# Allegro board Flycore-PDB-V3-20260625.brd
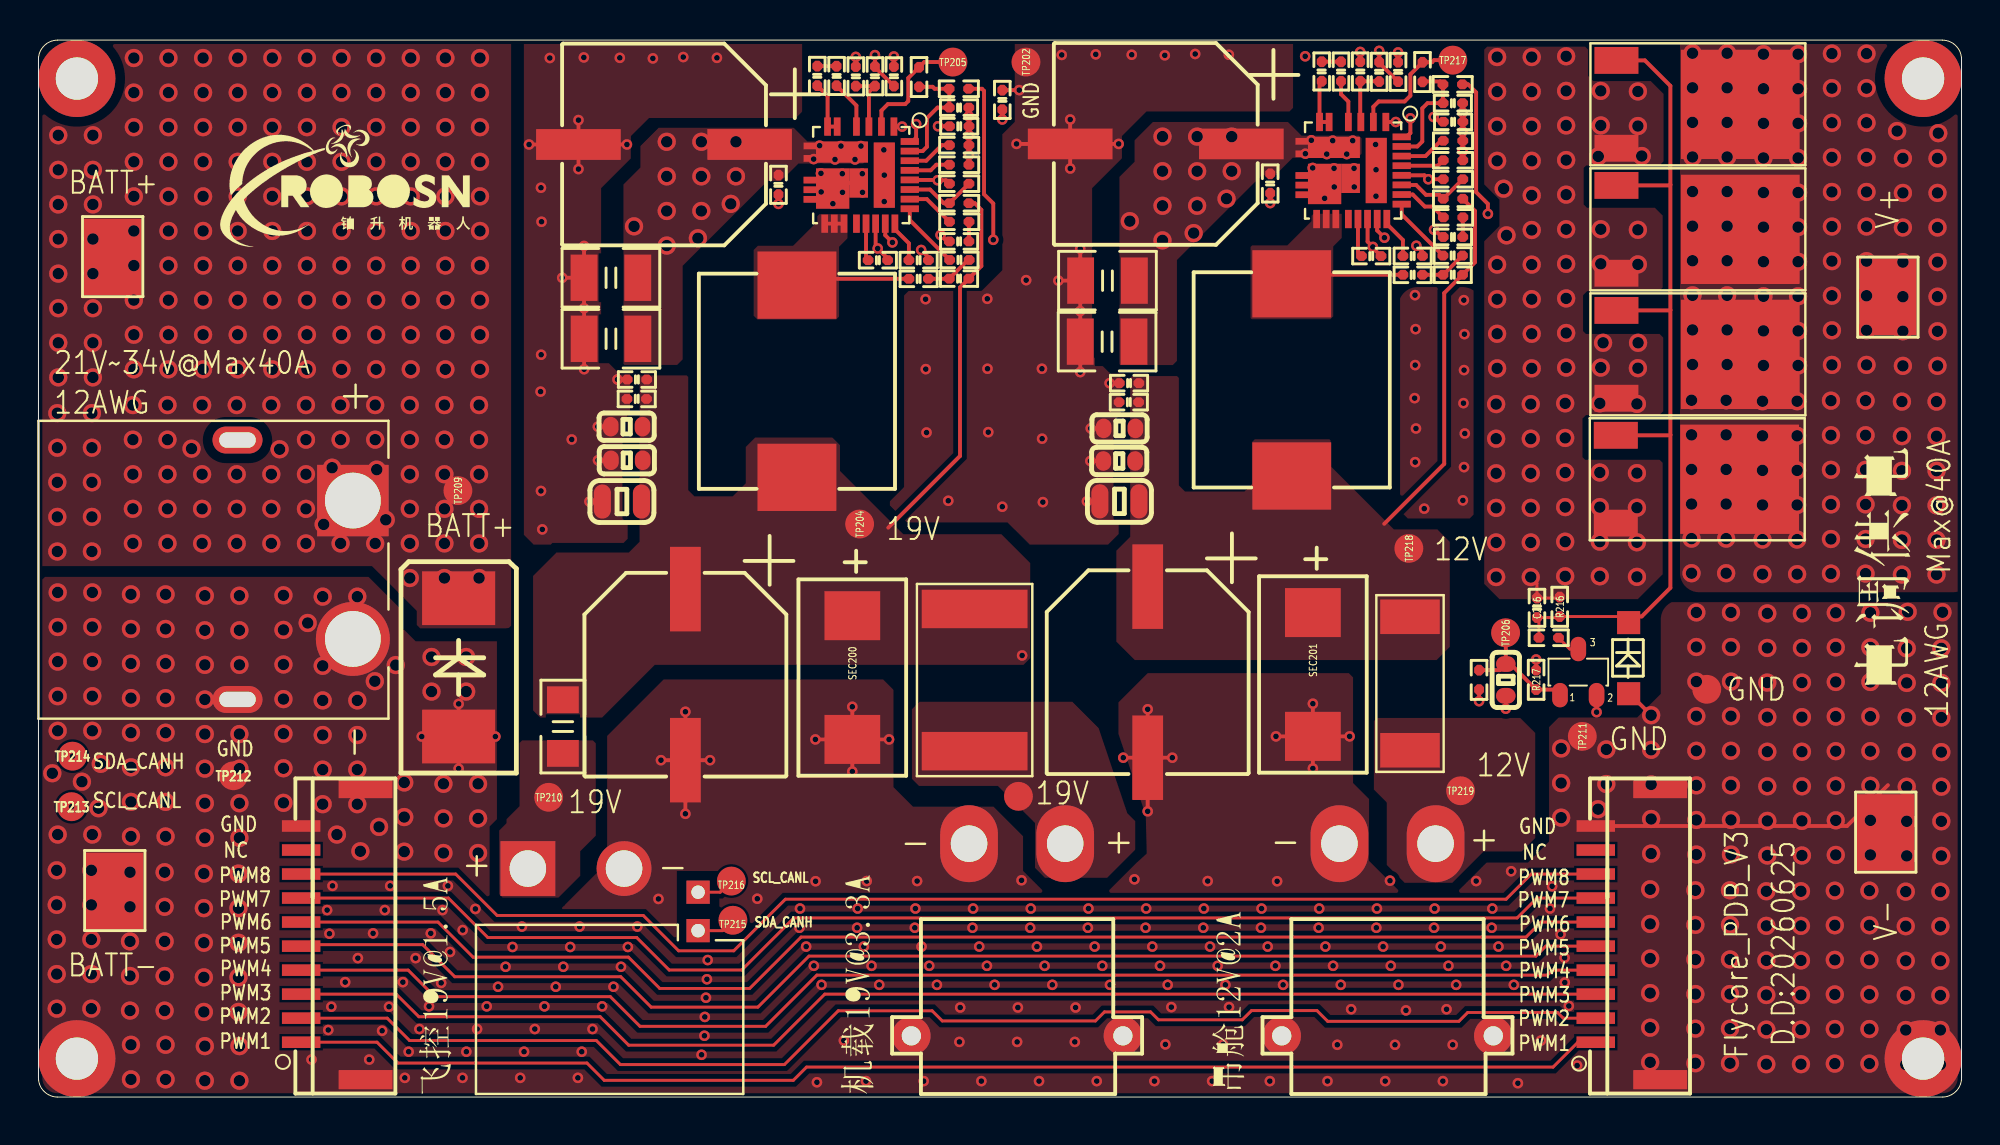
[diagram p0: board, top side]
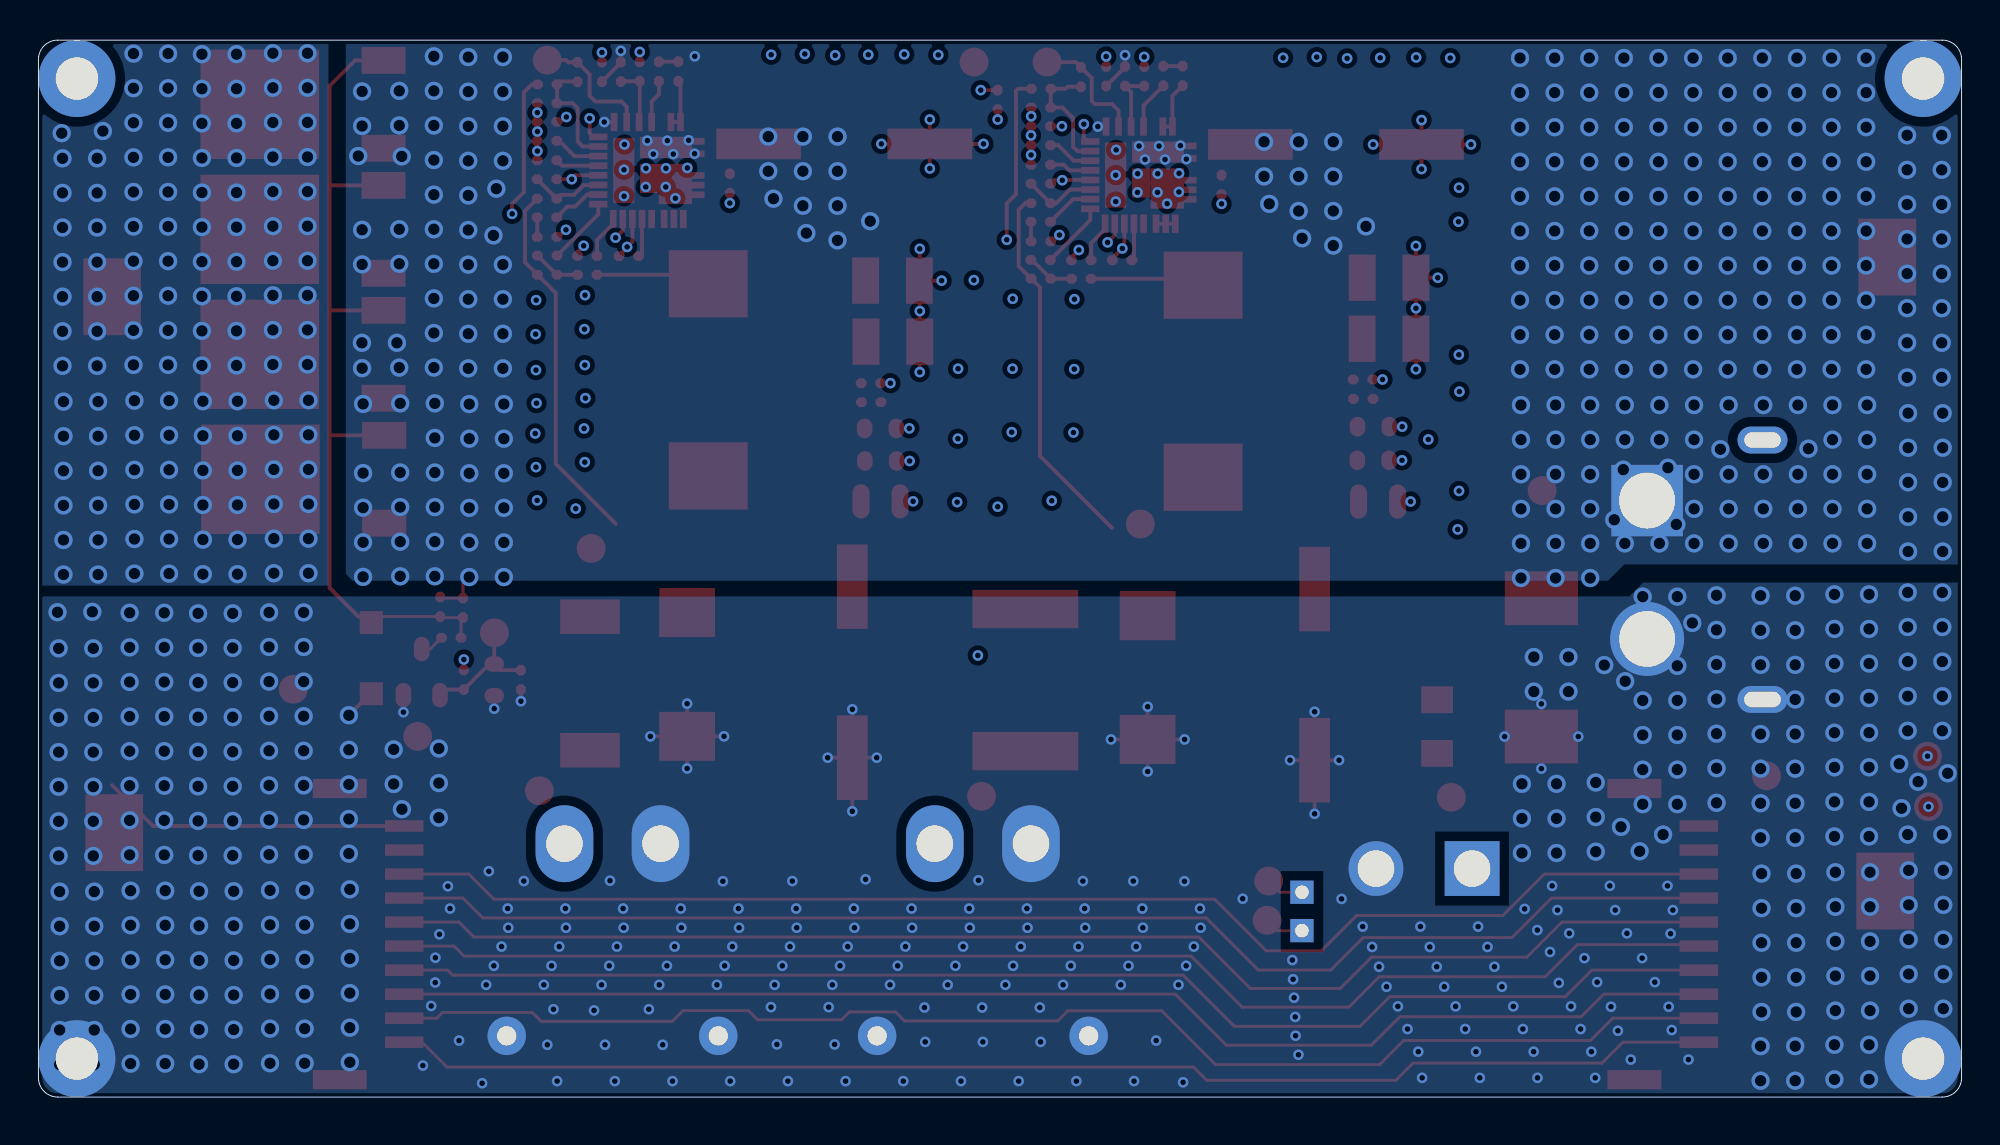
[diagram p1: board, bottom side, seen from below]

Outline 100 x 55 mm; copper layers: TOP, PWR02, PWR03, PWR04, PWR05, BOTTOM. Coordinates in mm from the lower left corner of the outline.
Outline path: 0,54 0,1 arc(0.29,0.29) 1,0 99,0 arc(99.71,0.29) 100,1 100,54 arc(99.71,54.71) 99,55 1,55 arc(0.29,54.71) 0,54

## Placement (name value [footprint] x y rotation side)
BATT+  TP-SMD  [TP_SMD_RECT_3R0X4R0]  3.86 43.71 90 top
BATT-  TP-SMD  [TP_SMD_RECT_3R0X4R0]  3.97 10.72 90 top
C202  10uF/100V  [C1210]  29.77 39.46 180 top
C203  10uF/100V  [C1210]  29.77 42.64 180 top
C204  .1U-100VX7-04-X  [C0402]  44.48 53.12 90 top
C205  1.8nF  [C0402]  47.87 42.59 180 top
C206  2.2nF  [C0402]  47.89 43.56 180 top
C207  .1U-50VX7-04-X  [C0402]  31.12 37.34 180 top
C208  10uF/35V  [C0603]  30.59 34.89 270 top
C209  10uF/35V  [C0603]  30.6 33.14 270 top
C210  10nF/50V  [C0402]  31.11 36.33 180 top
C211  22U-35VX5-08-X  [C0805]  30.34 30.99 90 top
C212  4.7U-10VX5-04-X  [C0402]  43.65 43.55 0 top
C213  470pF  [C0402]  47.87 44.53 0 top
C214  .1U-50VX7-04-X  [C0402]  41.5 53.14 90 top
C215  33nF/50V  [C0402]  45.77 43.55 0 top
C216  1uF/100V  [C0402]  77.92 25.46 90 top
C217  10uF/35V  [C0603]  76.3 21.71 0 top
C218  .1U-100VX7-04-X  [C0402]  38.48 47.47 270 top
C219  1.8nF  [C0402]  73.54 42.79 180 top
C220  10uF/35V  [C0603]  56.2 33.1 270 top
C221  10nF/50V  [C0402]  56.71 37.15 180 top
C222  10uF/100V  [C1210]  55.59 42.49 180 top
C223  2.2nF  [C0402]  73.54 43.79 180 top
C224  33nF/50V  [C0402]  71.46 43.77 0 top
C225  .1U-50VX7-04-X  [C0402]  67.73 53.37 90 top
C226  10uF/100V  [C1210]  55.57 39.31 180 top
C227  22U-35VX5-08-X  [C0805]  56.21 31 90 top
C228  4.7U-10VX5-04-X  [C0402]  69.3 43.76 0 top
C229  .1U-50VX7-04-X  [C0402]  56.7 36.16 180 top
C230  .1U-100VX7-04-X  [C0402]  64.05 47.54 270 top
C231  10uF/35V  [C0603]  56.22 34.8 270 top
C232  .1U-100VX7-04-X  [C0402]  70.7 53.35 90 top
C233  470pF  [C0402]  73.55 44.76 0 top
CAP201  68uF/100V  [CAP_SMD_330_D10]  32.53 49.57 180 top
CAP202  68uF/100V  [CAP_SMD_330_D10]  33.64 21.98 270 top
CAP207  68uF/100V  [CAP_SMD_330_D10]  58.1 49.6 180 top
CAP208  68uF/100V  [CAP_SMD_330_D10]  57.68 22.11 270 top
CON1  -  [XT30_M]  70.15 7.16 180 top
CON2  XT60_M  [AMASS_XT60PW-M]  10.35 27.44 270 top
CON201  XT30_M  [AMASS_XT30PW2]  29.7 4.56 0 top
CON204  GH1.25_10P  [GH1X25_10_LI]  16.36 8.48 90 top
CON215  GH1.25_10P  [GH1X25_10_LI]  83.68 8.48 90 top
CON216  -  [XT30_M]  50.89 7.16 180 top
D2  15V/500mW  [SOD-123]  82.69 22.84 270 top
F200  24V/3.3A/5.5A  [F8050]  48.68 21.7 270 top
H1  HOLE_3R20  [HOLE_PTH_2X0]  2 53 0 top
H2  HOLE_3R20  [HOLE_PTH_2X0]  2 2 0 top
H3  HOLE_3R20  [HOLE_PTH_2X0]  98 2 0 top
H4  HOLE_3R20  [HOLE_PTH_2X0]  98 53 180 top
L200  24V/1.5A/3A  [C1206]  27.27 19.28 270 top
L201  22uH  [L_11X15_10X85]  39.44 37.25 270 top
L202  22uH  [L_11X15_10X85]  65.17 37.32 270 top
L203  33V/2A/4A  [R2512]  71.32 21.52 270 top
NOREF  -  []  95.84 27.46 90 top
NOREF#2  -  []  20.62 5.66 90 top
NOREF#3  -  []  0 54 0 top
NOREF#4  -  []  0.99 -0.01 90 top
NOREF#5  -  []  61.86 4.84 90 top
NOREF#6  -  []  16.18 47.5 0 top
NOREF#7  -  []  42.57 5.75 90 top
Q202  PMOS/80V/70A/3.5mR  [TO252-3_4R56]  85.27 38.65 270 top
Q203  PMOS/80V/70A/3.5mR  [TO252-3_4R56]  85.27 45.16 270 top
Q204  Q_FET_N_ENH  [SOT23D132_1_2]  80.07 22.11 0 top
Q205  PMOS/80V/70A/3.5mR  [TO252-3_4R56]  85.27 51.66 270 top
Q206  PMOS/80V/70A/3.5mR  [TO252-3_4R56]  85.24 32.15 270 top
R185  0ohm  [C0402]  50.12 51.89 90 top
R204  100K-04  [C0402]  43.5 53.12 270 top
R205  11K  [C0402]  45.77 42.58 0 top
R206  100K-04  [C0402]  42.5 53.12 90 top
R207  232K  [R0402]  47.88 45.55 0 top
R208  60.4K  [R0402]  47.88 49.53 180 top
R209  3.3R  [C0402]  40.5 53.14 270 top
R210  232K  [R0402]  47.88 46.52 180 top
R211  330K  [R0402]  47.88 48.52 180 top
R212  2K  [C0402]  47.88 50.52 0 top
R213  0-04  [R0402]  47.86 52.47 180 top
R214  10K-04  [R0402]  47.88 47.53 180 top
R215  10K-04  [R0402]  45.79 53.08 270 top
R216  100K  [R0402]  79.11 25.51 90 top
R217  100K  [R0402]  77.88 21.71 90 top
R219  52.3K  [R0402]  74.91 21.71 90 top
R220  100K  [R0402]  78.53 23.9 0 top
R221  0-04  [R0402]  73.54 52.7 180 top
R222  2K  [C0402]  73.56 50.75 0 top
R223  232K  [R0402]  73.56 45.78 0 top
R224  10K-04  [R0402]  71.97 53.34 270 top
R225  11K  [C0402]  71.46 42.79 0 top
R226  10K-04  [R0402]  73.56 47.76 180 top
R227  232K  [R0402]  73.56 46.75 180 top
R228  100K-04  [C0402]  69.72 53.35 270 top
R229  3.3R  [C0402]  66.73 53.37 270 top
R230  60.4K  [R0402]  73.56 49.76 180 top
R231  330K  [R0402]  73.56 48.75 180 top
R232  100K-04  [C0402]  68.73 53.37 90 top
SC200  1U-16VX5-04-X  [C0402]  47.87 51.49 0 top
SC201  1U-16VX5-04-X  [C0402]  73.55 51.72 0 top
SEC200  100U-25V-40mR  [C7343]  42.32 21.83 270 top
SEC201  100U-25V-40mR  [C7343]  66.27 21.99 270 top
TP200  TP  [TESTPOINT_59MIL]  86.75 21.22 180 top
TP201  TP  [TESTPOINT_59MIL]  50.96 15.65 180 top
TP202  TP  [TESTPOINT_59MIL]  51.35 53.86 90 top
TP204  TP  [TESTPOINT_59MIL]  42.7 29.82 270 top
TP205  TP  [TESTPOINT_59MIL]  47.55 53.86 180 top
TP206  TP  [TESTPOINT_59MIL]  76.29 24.16 270 top
TP209  TP  [TESTPOINT_59MIL]  21.81 31.56 270 top
TP210  TP  [TESTPOINT_59MIL]  26.53 15.6 180 top
TP211  TP  [TESTPOINT_59MIL]  80.28 18.77 90 top
TP212  TP  [TESTPOINT_59MIL]  10.14 16.72 180 top
TP213  TP  [TESTPOINT_59MIL]  1.72 15.11 0 top
TP214  TP  [TESTPOINT_59MIL]  1.77 17.74 0 top
TP215  TP  [TESTPOINT_59MIL]  36.11 9.2 0 top
TP216  TP  [TESTPOINT_59MIL]  36.03 11.24 0 top
TP217  TP  [TESTPOINT_59MIL]  73.55 53.96 180 top
TP218  TP  [TESTPOINT_59MIL]  71.26 28.55 270 top
TP219  TP  [TESTPOINT_59MIL]  73.95 15.94 0 top
TVS8  Bi/36V/86A  [SMC_DO-214AB]  21.85 22.36 90 top
U200  SIC462ED-T1-GE3  [VREG_SIC462ED-T1-GE3]  42.78 47.98 270 top
U201  SIC462ED-T1-GE3  [VREG_SIC462ED-T1-GE3]  68.36 48.22 270 top
V+  TP-SMD  [TP_SMD_RECT_3R0X4R0]  96.17 41.65 270 top
V-  TP-SMD  [TP_SMD_RECT_3R0X4R0]  96.06 13.76 90 top

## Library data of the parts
BATT+ BATT- TP200-TP202 TP204-TP206 TP209-TP219 V+ V- = TP
C202-C210 C212-C215 C217-C226 C228-C233 = C#1
C211 C227 = C0805
C216 = CAP_0
CAP201 CAP202 CAP207 CAP208 = ECP_0
CON1 CON216 = XT30_M
CON2 = XT30_M_51
CON201 = XT30_M_46
CON204 CON215 = XT30_M_5
D2 = TVS_0
F200 = FUSE
H1-H4 = Hole
L200 L203 = INDUCTOR
L201 L202 = L
Q202 Q203 Q205 Q206 = PMOS-1
Q204 = Q_FET_N_ENH#1
R185 = R#1
R204-R217 R219-R232 = R
SC200 SC201 = C0402
SEC200 SEC201 = CAPACITOR POL_0
TVS8 = D_ESD
U200 U201 = SIC462ED-T1-GE3_7

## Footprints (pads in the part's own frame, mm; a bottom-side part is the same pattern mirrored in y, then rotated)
AMASS_XT30PW2
  rect 2.85x2.85 hole 1.9: 1(-4.25,7.33)
  round 2.85 hole 1.9: 2(0.75,7.33)
  rect 1.208x1.208 hole 0.7: 3(4.6,6.1) 4(4.6,4.1)
AMASS_XT60PW-M
  rect 3.716x3.716 hole 2.9: 1(-3.6,6)
  round 3.85 hole 2.9: 2(3.6,6)
  oval 1.4x2.6 hole 0.8x1.9: 3(-6.75,0) 4(6.75,0)
C0402
  custom 0.127x0.127 smd: 1(-0.508,0) 2(0.508,0)
C0603
  oval 1.016x0.813 smd: 1(0,0.826) 2(0,-0.826)
C0805
  oval 1.778x0.889 smd: 1(0,-1.016) 2(0,1.016)
C1206
  rect 1.397x1.651 smd: 1(-1.397,0) 2(1.397,0)
C1210
  rect 1.397x2.413 smd: 1(-1.397,0) 2(1.397,0)
C7343
  rect 2.55x2.9 smd: 1(-3.22,0) 2(3.22,0)
CAP_SMD_330_D10
  rect 4.4x1.6 smd: 1(-4.45,0) 2(4.45,0)
F8050
  rect 2x5.5 smd: 1(-3.7,0) 2(3.7,0)
GH1X25_10_LI
  rect 0.6x2 smd: 1(-5.625,2.7) 2(-4.375,2.7) 3(-3.125,2.7) 4(-1.875,2.7) 5(-0.625,2.7) 6(0.625,2.7) 7(1.875,2.7) 8(3.125,2.7) 9(4.375,2.7) 10(5.625,2.7)
  rect 1x2.8 smd: 11(-7.575,-0.65) 12(7.575,-0.65)
HOLE_PTH_2X0
  round 4 hole 2.2: 1(0,0)
L_11X15_10X85
  rect 3.5x4.1 smd: 1(-5,0) 2(5,0)
R0402
  custom 0.127x0.127 smd: 1(-0.508,0) 2(0.508,0)
R2512
  rect 1.8x3.1 smd: 1(-3.475,0) 2(3.475,0)
SMC_DO-214AB
  rect 2.8x3.8 smd: 1(3.6,0) 2(-3.6,0)
SOD-123
  rect 1.2x1.2 smd: 1(-1.85,0) 2(1.85,0)
SOT23D132_1_2
  oval 0.813x1.27 smd: 1(-0.95,-1.2) 2(0.95,-1.2) 3(0,1.2)
TESTPOINT_59MIL
  round 1.5 smd: 1(0,0)
TO252-3_4R56
  rect 1.397x2.286 smd: 1(-2.286,-3.219) 2(2.286,-3.219)
  rect 5.69x6.172 smd: 3(0,3.219)
TP_SMD_RECT_3R0X4R0
  rect 4x3 smd: 1(0,0)
VREG_SIC462ED-T1-GE3
  rect 0.95x0.35 smd: 1(-2.525,1.7) 2(-2.525,1.05) 3(-2.525,0.4) 4(-2.525,-0.25) 5(-2.525,-1.25) 6(-2.525,-1.75) 12(2.525,-1.9) 13(2.525,-1.4) 14(2.525,-0.9) 15(2.525,-0.25) 16(2.525,0.25) 17(2.525,0.75) 18(2.525,1.25) 19(2.525,1.75)
  rect 0.35x0.95 smd: 7(-1.52,-2.525) 8(-0.87,-2.525) 9(0.26,-2.525) 10(0.76,-2.525) 11(1.26,-2.525) 20(1.75,2.525) 21(1.25,2.525) 22(0.75,2.525) 23(0.25,2.525) 24(-0.25,2.525) 25(-0.75,2.525) 26(-1.25,2.525) 27(-1.75,2.525)
  rect 3.4x1.1 smd: 28(0,1.2)
  rect 1.1x2.7 smd: 29(-1.2,-1)
  rect 1.52x0.97 smd: 30(0.41,-0.135)
  rect 2.1x1.73 smd: 31(0.7,-1.485)
XT30_M
  oval 3x4 hole 1.9: 1(-2.5,-6.025) 2(2.5,-6.025)
  round 2 hole 1: 3(5.5,3.975) 4(-5.5,3.975)

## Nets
12V-OUT: CON1.1(VIN) L203.2 TP219.1
12V_EN: R228.2 R232.1 U201.3(EN)
19V_AIBOX_OUT: CON216.1(VIN) F200.2 TP201.1
19V_BOOT: C214.1 U200.4(BOOT)
19V_COMP: R207.1 U200.21(COMP)
19V_EN: R204.2 R206.1 U200.3(EN)
19V_FMU_OUT: CON201.1(VIN) L200.2 TP210.1
19V_FSW: R211.2 U200.24(FSW)
19V_ILIMIT: R208.2 U200.25(ILIMIT)
19V_MODE: R212.1 U200.27(MODE)
19V_PG: R215.1 TP205.1 U200.2(PGOOD)
19V_PHASE: R209.2 U200.5(PHASE) U200.6(PHASE__1)
19V_SW: L201.1 R205.1 U200.12(SW) U200.13(SW__1) U200.14(SW__2)
19V_ULTRA: R213.1 U200.18(ULTRASONIC)
19V_VDD: R213.2 R215.2 SC200.1 U200.26(VDD)
19V_VDRV: C212.1 U200.16(VDRV)
19V_VFB: R210.2 R214.1 U200.22(VFB)
19V_VSENS: C206.2 U200.20(VSNS)
AGND: C204.2 C213.1 C215.2 C224.2 C232.2 C233.1 R185.1 R208.1 R211.1 R212.2 R214.2 R222.2 R226.2 R230.1 R231.1 SC200.2 SC201.2 U200.23(AGND#23) U200.28(AGND#28) U201.23(AGND#23) U201.28(AGND#28)
GND: BATT-.1 C202.2 C203.2 C207.2 C208.2 C209.2 C210.2 C211.2 C212.2 C217.2 C218.2 C220.2 C221.2 C222.2 C226.2 C227.2 C228.2 C229.2 C230.2 C231.2 CAP201.2 CAP202.2 CAP207.2 CAP208.2 CON1.2(GND0) CON1.3(GND1) CON1.4(GND2) CON2.2(GND0) CON2.3(GND1) CON2.4(GND2) CON201.2(GND0) CON204.10 CON204.11(G1) CON204.12(G0) CON215.10 CON215.11(G1) CON215.12(G0) CON216.2(GND0) CON216.3(GND1) CON216.4(GND2) D2.2(ANODE) H1.1 H2.1 H3.1 H4.1 Q204.2(S) R185.2 R206.2 R219.1 R232.2 SEC200.2 SEC201.2 TP200.1 TP202.1 TP211.1 TP212.1 TVS8.2 U200.9(PGND#9) U200.10(PGND#10) U200.11(PGND#11) U200.17(PGND#17) U200.30(PGND#30) U200.31(PGND#31) U201.9(PGND#9) U201.10(PGND#10) U201.11(PGND#11) U201.17(PGND#17) U201.30(PGND#30) U201.31(PGND#31) V-.1
VBAT_ESC: Q202.3(D) Q203.3(D) Q205.3(D) Q206.3(D) V+.1
VDD: R221.2 R224.2 SC201.1 U201.26(VDD)
VDD_12V_SYS: C219.1 C220.1 C221.1 C227.1 C229.1 C231.1 CAP208.1 L202.2 L203.1 R227.1 SEC201.1 TP218.1
VDD_19V_SYS: C205.1 C207.1 C208.1 C209.1 C210.1 C211.1 CAP202.1 F200.1 L200.1 L201.2 R210.1 R217.2 SEC200.1 TP204.1
BATT_IN: BATT+.1 C202.1 C203.1 C204.1 C216.2 C218.1 C222.1 C226.1 C230.1 C232.1 CAP201.1 CAP207.1 CON2.1(V+) Q202.2(S) Q203.2(S) Q205.2(S) Q206.2(S) R204.1 R216.2 R228.1 TP209.1 TVS8.1 U200.1(VCIN) U200.7(VIN#7) U200.8(VIN#8) U200.29(VIN#29) U201.1(VCIN) U201.7(VIN#7) U201.8(VIN#8) U201.29(VIN#29)
BOOT: C225.1 U201.4(BOOT)
CANH_SCL: CON201.3(S1) TP213.1 TP216.1
CANL_SDA: CON201.4(S2) TP214.1 TP215.1
COMP: R223.1 U201.21(COMP)
ESC_EN: C216.1 D2.1(CATHODE) Q202.1(G) Q203.1(G) Q205.1(G) Q206.1(G) R216.1 R220.1
FSW: R231.2 U201.24(FSW)
ILIMIT: R230.2 U201.25(ILIMIT)
MODE: R222.1 U201.27(MODE)
PHASE: R229.2 U201.5(PHASE) U201.6(PHASE__1)
PWM1: CON204.1 CON215.1
PWM2: CON204.2 CON215.2
PWM3: CON204.3 CON215.3
PWM4: CON204.4 CON215.4
PWM5: CON204.5 CON215.5
PWM6: CON204.6 CON215.6
PWM7: CON204.7 CON215.7
PWM8: CON204.8 CON215.8
SW: L202.1 R225.1 U201.12(SW) U201.13(SW__1) U201.14(SW__2)
ULTRA: R221.1 U201.18(ULTRASONIC)
VDRV: C228.1 U201.16(VDRV)
VFB: R226.1 R227.2 U201.22(VFB)
VSENS: C223.2 U201.20(VSNS)
X86_PWR_EN: R224.1 TP217.1 U201.2(PGOOD)
N8283759: C217.1 Q204.1(G) R217.1 R219.2 TP206.1
N15887710: Q204.3(D) R220.2
N17213433: CON215.9
N17213475: CON204.9
N17226372: C205.2 C206.1 R205.2
N17226390: C213.2 R207.2
N17226393: C214.2 R209.1
N17226422: C215.1 U200.19(SS)
N17229988: C219.2 C223.1 R225.2
N17230026: C233.2 R223.2
N17230033: C225.2 R229.1
N17230097: C224.1 U201.19(SS)

Pads without a net: U200 15; U201 15

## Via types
v1: diameter 0.55, hole 0.3, TOP to BOTTOM, 334 vias
v2: diameter 0.95, hole 0.6, TOP to BOTTOM, 664 vias

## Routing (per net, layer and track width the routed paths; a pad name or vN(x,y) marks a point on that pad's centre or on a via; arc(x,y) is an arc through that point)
12V_EN: length 3.1
  TOP w0.2: R228.2 69.7,52.86 R232.1 68.73,50.77 U201.3
19V_BOOT: length 2.6
  TOP w0.2: U200.4 42.53,51.6 C214.1
19V_COMP: length 2.6
  TOP w0.2: R207.1 46.2,46.73 U200.21
19V_EN: length 3.2
  TOP w0.2: R204.2 43.49,52.61 ; 43.49,52.61 R206.1 ; 43.49,52.61 43.18,52.3 U200.3
19V_FSW: length 2.2
  TOP w0.2: R211.2 46.69,48.52 46.4,48.23 U200.24
19V_ILIMIT: length 2.4
  TOP w0.2: U200.25 46.17,48.73 46.97,49.53 R208.2
19V_MODE: length 2.9
  TOP w0.2: U200.27 45.44,49.73 45.64,49.93 v1(45.64,50.63) ; R212.1 v1(46.78,50.52)
  PWR03 w0.2: v1(46.78,50.52) 46.67,50.63 v1(45.64,50.63)
19V_PG: length 6.3
  TOP w0.2: TP205.1 46.06,53.86 R215.1 45.23,53.03 45.23,51.83 45.07,51.67 44.17,51.67 43.83,51.33 U200.2
19V_PHASE: length 2.9
  TOP w0.2: R209.2 41.03,52.1 U200.6 U200.5
19V_SW: length 7
  TOP w0.2: U200.14 U200.13 U200.12 ; L201.1 39.77,42.58 R205.1
19V_ULTRA: length 16.1
  TOP w0.2: R213.1 49.06,52.47 49.17,52.36 49.17,46.98 49.65,46.5 v1(49.65,44.61) ; U200.18 44.03,44.85 v1(44.41,44.48)
  PWR03 w0.2: v1(49.65,44.61) 48.49,43.45 45.43,43.45 v1(44.41,44.48)
19V_VDD: length 6.5
  TOP w0.2: U200.26 45.98,49.23 46.2,49.45 46.2,50.94 46.75,51.49 SC200.1 47.36,52.46 R213.2 46.6,52.47 46.5,52.57 R215.2
19V_VDRV: length 1.9
  TOP w0.2: U200.16 43.03,43.66 C212.1
19V_VFB: length 3.8
  TOP w0.2: U200.22 46.36,47.23 47.08,46.52 R210.2 R214.1
19V_VSENS: length 3.5
  TOP w0.2: U200.20 45.31,45.64 C206.2
AGND: length 14.5
  TOP w0.2: SC201.2 v1(74.06,51.23) 74.06,50.76 R222.2 74.05,50.74 v1(74.05,50.24) 74.05,49.77 R230.1 74.05,49.75 v1(74.05,49.23) 74.06,49.22 R231.1 ; C233.1 72.98,44.76 72.61,45.13 v1(72.57,45.13) ; SC200.2 v1(48.38,51.04) 48.39,51.03 R212.2 v1(48.39,50.04) 48.38,50.04 R208.1 v1(48.38,49.02) R211.1 ; v1(71.65,44.3) 71.97,43.98 C224.2 ; C204.2 v1(44.48,54.15) ; 70.89,47.97 72.07,47.97 v1(72.27,47.76) R226.2 ; C232.2 v1(70.7,54.36) ; C215.2 46.28,43.7 v1(45.9,44.08) ; U200.23 46.74,47.73 v1(46.76,47.71) 47.19,47.71 R214.2 ; C213.1 47.24,44.53 v1(46.91,44.86) ; R185.1 v1(50.12,50.87)
  vias: v1(43.96,49.29) v1(43.98,47.98) v1(43.98,46.6) v1(69.53,49.57) v1(69.55,46.88) v1(69.55,48.26)
GND: length 108.6
  TOP w0.2: TVS8.2 v1(21.85,20.46) ; TVS8.2 v1(21.85,17.09) ; TVS8.2 v1(19.93,18.76) ; TVS8.2 v1(23.76,18.76) ; v1(53.04,42.49) 54.17,42.49 ; 54.17,42.49 v1(54.17,40.9) ; 54.17,42.49 v1(54.17,44.14) ; C231.2 v1(54.72,34.8) ; D2.2 82.74,20.99 v2(83.86,19.87) ; CAP208.2 v1(58.96,17.66) ; CAP208.2 v1(57.68,20.18) ; CAP208.2 v1(57.68,14.87) ; CAP208.2 v1(56.41,17.66) ; R232.2 v1(68.73,54.39) ; C208.2 v1(29.09,34.89) ; SEC201.2 v1(64.35,18.77) ; SEC201.2 v1(66.27,20.47) ; SEC201.2 v1(68.18,18.77) ; SEC201.2 v1(66.27,17.1) ; C203.2 v1(28.37,44.29) ; C203.2 v1(28.37,41.05) ; C203.2 v1(27.24,42.64) ; U201.17 69.11,44.52 v1(69.39,44.24) 69.39,44.19 C228.2 ; SEC200.2 v1(42.32,16.94) ; SEC200.2 v1(44.23,18.61) ; SEC200.2 v1(40.4,18.61) ; SEC200.2 v1(42.32,20.31) ; C218.2 v1(38.48,46.48) ; R219.1 v1(74.91,20.6) ; CAP201.2 v1(30.6,49.57) ; CAP201.2 v1(28.08,48.29) ; CAP201.2 v1(25.51,49.57) ; CAP201.2 v1(28.08,50.84) ; U200.10 41.24,47.22 ; 41.24,47.22 40.74,46.72 U200.11 ; 41.24,47.22 U200.31 ; U200.9 40.86,47.72 U200.31 ; U201.9 66.44,47.96 U201.31 66.82,47.46 ; C207.2 v1(30.11,37.34) ; R185.2 51,52.4 v1(51,52.4) ; 54.17,40.97 C226.2 v1(54.17,37.72) ; C211.2 v1(28.65,30.99) ; U200.17 43.53,44.27 v1(43.64,44.16) 44.16,43.64 C212.2 ; 66.82,47.46 66.32,46.96 U201.11 ; 66.82,47.46 U201.10 ; CAP207.2 v1(53.65,48.32) ; CAP207.2 v1(50.86,49.6) ; CAP207.2 v1(56.17,49.6) ; CAP207.2 v1(53.65,50.87) ; CAP202.2 v1(32.37,17.53) ; CAP202.2 v1(34.92,17.53) ; CAP202.2 v1(33.64,20.05) ; CAP202.2 v1(33.64,14.74) ; 28.37,41.12 C202.2 v1(28.37,37.87) ; C230.2 v1(64.05,46.52) ; C227.2 v1(54.52,31) ; C220.2 v1(54.7,33.1) ; U200.31 41.59,47.57 U200.30 ; R206.2 v1(42.5,54.13) ; C209.2 v1(29.1,33.14) ; 96.17,16.23 94.05,14.11 CON215.10 ; C221.2 v1(55.7,37.15) ; Q204.2 v1(81.02,20.03) ; C217.2 v1(76.3,20.21)
  vias: v1(14.2,1.95) v1(15.01,9.73) v1(15.13,8.5) v1(15.07,3.49) v1(15.23,4.7) v1(15.29,10.99) v1(15.95,5.98) v1(16.61,7.23) v1(17.2,1.95) v1(17.4,8.52) v1(17.87,3.45) v1(18.01,9.73) v1(18.23,4.7) v1(18.29,10.99) v1(18.95,5.98) v1(19.05,1) v1(19.25,2.36) v1(19.61,7.23) v1(19.81,3.54) v1(20.31,4.72) v1(20.4,8.52) v1(20.94,5.94) v1(21.01,9.73) v1(21.29,10.99) v1(21.4,7.55) v1(22.06,8.69) v1(22.05,1) v1(22.25,2.36) v1(22.72,9.79) v1(22.81,3.54) v1(23.31,4.72) v1(23.9,5.74) v1(24.29,6.78) v1(24.65,7.81) v1(25.14,8.87) v1(25.05,1) v1(25.25,2.36) v1(25.81,3.54) v1(26.13,47.32) v1(26.14,38.63) v1(26.11,36.71) v1(26.13,31.54) v1(26.16,45.55) v1(26.2,29.54) v1(26.31,4.72) v1(26.59,54.07) v1(26.9,5.74) v1(27.29,6.78) v1(27.65,7.81) v1(27.73,34.22) v1(28.14,8.87) v1(28.05,1) v1(28.25,2.36) v1(28.36,54.1) v1(28.81,3.54) v1(29.31,4.72) v1(29.9,5.74) v1(30.23,54.08) v1(30.29,6.78) v1(30.65,7.81) v1(31.14,8.87) v1(31.95,54.05) v1(32.24,10.31) v1(33.53,54.12) v1(34.48,2.2) v1(34.65,4.17) v1(34.63,3.19) v1(34.71,5.17) v1(34.8,7.13) v1(34.76,6.13) v1(35.28,54.08) v1(37.38,10.32) v1(39.6,9.81) v1(39.57,8.81) v1(39.92,7.83) v1(40.32,6.83) v1(40.41,11.23) v1(40.48,0.77) v1(40.69,48.07) v1(40.7,47.1) v1(40.72,5.84) v1(41.31,46.49) v1(41.8,48.05) v1(41.81,47.08) v1(41.88,2.94) v1(42.6,9.81) v1(42.57,8.81) v1(42.84,48.05) v1(42.85,47.08) v1(42.92,7.83) v1(43.03,0.83) v1(43.07,11.24) v1(43.32,6.83) v1(43.72,5.84) v1(45.6,9.81) v1(45.57,8.81) v1(45.69,11.24) v1(45.92,7.83) v1(46.03,0.83) v1(46.13,41.52) v1(46.14,37.88) v1(46.18,34.58) v1(46.32,6.83) v1(46.72,5.84) v1(47.31,31.03) v1(47.93,4.66) v1(47.89,2.87) v1(48.6,9.81) v1(48.57,8.81) v1(48.92,7.83) v1(49.03,0.83) v1(49.34,41.54) v1(49.32,6.83) v1(49.35,37.9) v1(49.39,34.6) v1(49.72,5.84) v1(50.12,30.72) v1(50.93,4.66) v1(50.89,2.87) v1(51.12,11.28) v1(51.36,42.51) v1(51.6,9.81) v1(51.57,8.81) v1(51.92,7.83) v1(52.03,0.83) v1(52.18,37.9) v1(52.19,34.26) v1(52.23,30.96) v1(52.32,6.83) v1(52.72,5.84) v1(53.21,54.23) v1(53.93,4.66) v1(53.89,2.87) v1(54.6,9.81) v1(54.57,8.81) v1(54.92,7.83) v1(54.98,54.26) v1(55.03,0.83) v1(55.32,6.83) v1(55.72,5.84) v1(56.85,54.24) v1(56.99,11.33) v1(57.6,9.81) v1(57.57,8.81) v1(57.92,7.83) v1(58.03,0.83) v1(58.32,6.83) v1(58.57,54.21) v1(58.6,2.74) v1(58.72,5.84) v1(58.91,4.68) v1(60.15,54.28) v1(60.6,9.81) v1(60.57,8.81) v1(60.8,11.24) v1(60.92,7.83) v1(61.03,0.83) v1(61.32,6.83) v1(61.6,2.74) v1(61.72,5.84) v1(61.9,54.24) v1(61.91,4.68) v1(63.6,9.81) v1(63.57,8.81) v1(63.92,7.83) v1(64.03,0.83) v1(64.32,6.83) v1(64.41,11.23) v1(64.72,5.84) v1(66.26,48.35) v1(66.6,9.81) v1(66.57,8.81) v1(66.88,46.77) v1(66.92,7.83) v1(67.03,0.83) v1(67.32,6.83) v1(67.37,48.33) v1(67.38,47.36) v1(67.54,2.72) v1(67.72,5.84) v1(68.26,4.57) v1(68.41,48.33) v1(68.42,47.36) v1(69.6,9.81) v1(69.57,8.81) v1(69.92,7.83) v1(70.03,0.83) v1(70.28,11.26) v1(70.32,6.83) v1(70.54,2.72) v1(70.72,5.84) v1(71.11,4.51) v1(71.58,41.73) v1(71.61,39.96) v1(71.59,38.09) v1(71.56,36.37) v1(71.63,34.79) v1(71.59,33.04) v1(72.06,30.62) v1(72.6,9.81) v1(72.57,8.81) v1(72.92,7.83) v1(73.03,0.83) v1(73.22,4.57) v1(73.32,6.83) v1(73.54,2.72) v1(73.72,5.84) v1(74.12,41.47) v1(74.13,37.83) v1(74.1,36.11) v1(74.13,32.78) v1(74.07,31.05) v1(74.15,39.7) v1(74.17,34.53) v1(74.76,11.24) v1(75.6,9.81) v1(75.57,8.81) v1(75.92,7.83) v1(76.32,6.83) v1(76.58,11.75) v1(76.72,5.84) v1(76.93,0.72) v1(78.13,2.94) v1(78.6,9.81) v1(78.71,10.97) v1(79.15,8.47) v1(79.36,7.25) v1(79.37,5.96) v1(79.58,4.74) v1(80.01,1.64) v2(0.72,16.85) v2(0.95,11.8) v2(0.95,10) v2(0.95,8.2) v2(0.95,6.4) v2(0.95,4.6) v2(1,26.26) v2(1,24.46) v2(1,22.66) v2(1,20.86) v2(1,19.06) v2(1,13.66) v2(2.26,16.41) v2(2.8,26.26) v2(2.8,24.46) v2(2.8,22.66) v2(2.8,20.86) v2(2.8,19.06) v2(2.8,13.66) v2(2.75,11.8) v2(2.75,10) v2(2.75,8.2) v2(2.75,6.4) v2(2.75,4.6) v2(3.12,15.03) v2(3.24,17.34) v2(4.81,26.16) v2(4.81,24.36) v2(4.81,22.56) v2(4.81,20.76) v2(4.81,18.96) v2(4.81,17.16) v2(4.81,15.36) v2(4.81,13.56) v2(4.76,11.7) v2(4.76,9.9) v2(4.76,8.1) v2(4.76,6.3) v2(4.76,4.5) v2(4.81,2.72) v2(4.81,0.92) v2(6.61,26.16) v2(6.61,24.36) v2(6.61,22.56) v2(6.61,20.76) v2(6.61,18.96) v2(6.61,17.16) v2(6.61,15.36) v2(6.61,13.56) v2(6.56,11.7) v2(6.56,9.9) v2(6.56,8.1) v2(6.56,6.3) v2(6.56,4.5) v2(6.61,2.72) v2(6.61,0.92) v2(8.6,11.63) v2(8.6,9.83) v2(8.6,8.03) v2(8.6,6.23) v2(8.6,4.43) v2(8.65,26.09) v2(8.65,24.29) v2(8.65,22.49) v2(8.65,20.69) v2(8.65,18.89) v2(8.65,17.09) v2(8.65,15.29) v2(8.65,13.49) v2(8.65,2.65) v2(8.65,0.85) v2(10.45,26.09) v2(10.45,24.29) v2(10.45,22.49) v2(10.45,18.89) v2(10.45,17.09) v2(10.45,15.29) v2(10.45,13.49) v2(10.4,11.63) v2(10.4,9.83) v2(10.4,8.03) v2(10.4,6.23) v2(10.4,4.43) v2(10.45,2.65) v2(10.45,0.85) v2(12.74,26.11) v2(12.74,24.31) v2(12.74,22.51) v2(12.74,20.71) v2(12.74,18.91) v2(12.74,17.11) v2(12.74,15.31) v2(14,24.67) v2(14.78,26.04) v2(14.78,22.44) v2(14.78,20.64) v2(14.78,18.84) v2(14.78,17.04) v2(14.78,15.24) v2(15.52,13.66) v2(16.58,26.04) v2(16.58,20.64) v2(16.58,18.84) v2(16.58,17.04) v2(16.58,15.24) v2(16.74,12.79) v2(17.49,21.64) v2(17.71,14.06) v2(18.58,22.48) v2(19.02,16.37) v2(19.02,14.57) v2(19.02,12.77) v2(20.44,22.9) v2(20.44,21.1) v2(21.06,16.3) v2(21.06,14.5) v2(21.06,12.7) v2(22.24,22.9) v2(22.24,21.1) v2(22.86,16.3) v2(22.86,14.5) v2(22.86,12.7) v2(79.18,18.14) v2(79.18,16.34) v2(79.18,14.54) v2(81.1,14.98) v2(81.53,18.09) v2(81.53,16.29) v2(83.81,10.81) v2(83.81,9.01) v2(83.81,7.21) v2(83.81,5.41) v2(83.81,3.61) v2(83.81,1.81) v2(83.86,18.07) v2(83.86,16.27) v2(83.86,14.47) v2(83.86,12.67) v2(86.21,25.22) v2(86.21,23.42) v2(86.21,21.62) v2(86.21,19.82) v2(86.21,18.02) v2(86.21,16.22) v2(86.21,14.42) v2(86.21,12.62) v2(86.16,10.76) v2(86.16,8.96) v2(86.16,7.16) v2(86.16,5.36) v2(86.16,3.56) v2(86.16,1.76) v2(88.01,25.22) v2(88.01,23.42) v2(88.01,21.62) v2(88.01,19.82) v2(88.01,18.02) v2(88.01,16.22) v2(88.01,14.42) v2(88.01,12.62) v2(87.96,10.76) v2(87.96,8.96) v2(87.96,7.16) v2(87.96,5.36) v2(87.96,3.56) v2(87.96,1.76) v2(89.85,10.71) v2(89.85,8.91) v2(89.85,7.11) v2(89.85,5.31) v2(89.85,3.51) v2(89.85,1.71) v2(89.9,25.17) v2(89.9,23.37) v2(89.9,21.57) v2(89.9,19.77) v2(89.9,17.97) v2(89.9,16.17) v2(89.9,14.37) v2(89.9,12.57) v2(91.7,25.17) v2(91.7,23.37) v2(91.7,21.57) v2(91.7,19.77) v2(91.7,17.97) v2(91.7,16.17) v2(91.7,14.37) v2(91.7,12.57) v2(91.65,10.71) v2(91.65,8.91) v2(91.65,7.11) v2(91.65,5.31) v2(91.65,3.51) v2(91.65,1.71) v2(93.41,10.74) v2(93.41,8.94) v2(93.41,7.14) v2(93.41,5.34) v2(93.41,3.54) v2(93.41,1.74) v2(93.46,25.2) v2(93.46,23.4) v2(93.46,21.6) v2(93.46,19.8) v2(93.46,18) v2(93.46,16.2) v2(93.46,14.4) v2(93.46,12.6) v2(95.21,10.74) v2(95.21,8.94) v2(95.21,7.14) v2(95.21,5.34) v2(95.21,3.54) v2(95.21,1.74) v2(95.26,25.2) v2(95.26,23.4) v2(95.26,21.6) v2(95.26,19.8) v2(95.26,18) v2(95.26,16.2) v2(95.26,14.4) v2(95.26,12.6) v2(97.1,10.69) v2(97.1,8.89) v2(97.1,7.09) v2(97.1,5.29) v2(97.1,3.49) v2(97.1,1.69) v2(97.2,25.25) v2(97.15,23.35) v2(97.15,21.55) v2(97.15,19.75) v2(97.15,17.95) v2(97.15,16.15) v2(97.15,14.35) v2(97.15,12.55) v2(98.9,10.69) v2(98.9,8.89) v2(98.9,7.09) v2(98.9,5.29) v2(98.9,3.49) v2(98.9,1.69) v2(99.01,25.23) v2(98.95,23.35) v2(98.95,21.55) v2(98.95,19.75) v2(98.95,17.95) v2(98.95,16.15) v2(98.95,14.35) v2(98.95,12.55)
VBAT_ESC:
  vias: v2(86.01,54.32) v2(86.01,52.52) v2(86.01,50.72) v2(86.01,48.92) v2(86.01,47.12) v2(86.01,45.32) v2(86.01,43.52) v2(86.01,41.72) v2(86.01,39.92) v2(86.01,38.12) v2(85.96,36.26) v2(85.96,34.46) v2(85.96,32.66) v2(85.96,30.86) v2(85.96,29.06) v2(85.96,27.26) v2(87.81,54.32) v2(87.81,52.52) v2(87.81,50.72) v2(87.81,48.92) v2(87.81,47.12) v2(87.81,45.32) v2(87.81,43.52) v2(87.81,41.72) v2(87.81,39.92) v2(87.81,38.12) v2(87.76,36.26) v2(87.76,34.46) v2(87.76,32.66) v2(87.76,30.86) v2(87.76,29.06) v2(87.76,27.26) v2(89.7,54.27) v2(89.7,52.47) v2(89.7,50.67) v2(89.7,48.87) v2(89.7,47.07) v2(89.7,45.27) v2(89.7,43.47) v2(89.7,41.67) v2(89.7,39.87) v2(89.7,38.07) v2(89.65,36.21) v2(89.65,34.41) v2(89.65,32.61) v2(89.65,30.81) v2(89.65,29.01) v2(89.65,27.21) v2(91.5,54.27) v2(91.5,52.47) v2(91.5,50.67) v2(91.5,48.87) v2(91.5,47.07) v2(91.5,45.27) v2(91.5,43.47) v2(91.5,41.67) v2(91.5,39.87) v2(91.5,38.07) v2(91.45,36.21) v2(91.45,34.41) v2(91.45,32.61) v2(91.45,30.81) v2(91.45,29.01) v2(91.45,27.21) v2(93.21,36.24) v2(93.21,34.44) v2(93.21,32.64) v2(93.21,30.84) v2(93.21,29.04) v2(93.21,27.24) v2(93.26,54.3) v2(93.26,52.5) v2(93.26,50.7) v2(93.26,48.9) v2(93.26,47.1) v2(93.26,45.3) v2(93.26,43.5) v2(93.26,41.7) v2(93.26,39.9) v2(93.26,38.1) v2(95.01,36.24) v2(95.01,34.44) v2(95.01,32.64) v2(95.01,30.84) v2(95.01,29.04) v2(95.01,27.24) v2(95.06,54.3) v2(95.06,52.5) v2(95.06,50.7) v2(95.06,48.9) v2(95.06,47.1) v2(95.06,45.3) v2(95.06,43.5) v2(95.06,41.7) v2(95.06,39.9) v2(95.06,38.1) v2(96.65,50.27) v2(96.9,36.19) v2(96.9,34.39) v2(96.9,32.59) v2(96.9,30.79) v2(96.9,28.99) v2(96.9,27.19) v2(96.95,48.85) v2(96.95,47.05) v2(96.95,45.25) v2(96.95,43.45) v2(96.95,41.65) v2(96.95,39.85) v2(96.95,38.05) v2(98.7,36.19) v2(98.7,34.39) v2(98.7,32.59) v2(98.7,30.79) v2(98.7,28.99) v2(98.7,27.19) v2(98.79,50.16) v2(98.75,48.85) v2(98.75,47.05) v2(98.75,45.25) v2(98.75,43.45) v2(98.75,41.65) v2(98.75,39.85) v2(98.75,38.05)
VDD: length 6.2
  TOP w0.2: R224.2 71.99,52.85 72.88,52.85 R221.2 73.03,51.73 SC201.1 72.23,51.72 71.96,51.45 71.96,49.73 71.7,49.47 70.89,49.47
VDD_12V_SYS: length 19.1
  TOP w0.2: 69.98,29.83 73.1,32.95 73.1,41.84 C219.1 74.7,43.44 74.7,46.11 R227.1
VDD_19V_SYS: length 46.7
  TOP w0.152: R217.2 v1(77.88,22.77)
  TOP w0.2: 44.19,29.63 47.92,33.36 47.92,42.13 C205.1 49.03,43.24 49.03,46.17 48.68,46.52 R210.1
  PWR03 w0.2: v1(77.88,22.77) 77.67,22.98 v1(51.15,22.98)
BATT_IN: length 15.5
  TOP w0.152: R216.2 79.05,25.97 C216.2 77.92,26.74 v2(77.6,27.06) ; v2(83.37,48.97) 82.97,49.37 Q205.2
  TOP w0.2: U200.1 v1(44.91,50.5) ; C204.1 43.5,53.59 v1(43.5,54.22) ; v1(69.72,54.44) R228.1 69.72,53.82 C232.1 ; U200.8 41.45,48.85 U200.29 41.46,49.5 U200.7 ; U201.8 67.03,49.09 U201.29 67.04,49.74 U201.7 ; v1(70.58,50.74) U201.1
  vias: v1(40.31,48.81) v1(40.62,49.51) v1(41.42,48.79) v1(41.73,49.49) v1(42.46,48.79) v1(42.77,49.49) v1(65.87,54.16) v1(65.88,49.09) v1(66.19,49.79) v1(66.99,49.07) v1(67.3,49.77) v1(68.03,49.07) v1(68.34,49.77) v2(1.03,50.05) v2(1.03,48.25) v2(1.03,46.45) v2(1.03,44.65) v2(1.03,42.85) v2(1.03,41.05) v2(1.03,39.25) v2(1.03,37.45) v2(0.98,35.59) v2(0.98,33.79) v2(0.98,31.99) v2(0.98,30.19) v2(0.98,28.39) v2(2.83,50.05) v2(2.83,48.25) v2(2.83,46.45) v2(2.83,44.65) v2(2.83,42.85) v2(2.83,41.05) v2(2.83,39.25) v2(2.83,37.45) v2(2.78,35.59) v2(2.78,33.79) v2(2.78,31.99) v2(2.78,30.19) v2(2.78,28.39) v2(4.91,36.01) v2(4.91,34.21) v2(4.91,32.41) v2(4.91,30.61) v2(4.91,28.81) v2(4.96,54.07) v2(4.96,52.27) v2(4.96,50.47) v2(4.96,48.67) v2(4.96,46.87) v2(4.96,45.07) v2(4.96,43.27) v2(4.96,41.47) v2(4.96,39.67) v2(4.96,37.87) v2(6.71,36.01) v2(6.71,34.21) v2(6.71,32.41) v2(6.71,30.61) v2(6.71,28.81) v2(6.76,54.07) v2(6.76,52.27) v2(6.76,50.47) v2(6.76,48.67) v2(6.76,46.87) v2(6.76,45.07) v2(6.76,43.27) v2(6.76,41.47) v2(6.76,39.67) v2(6.76,37.87) v2(7.96,33.74) v2(8.51,36.01) v2(8.51,32.41) v2(8.51,30.61) v2(8.51,28.81) v2(8.56,54.07) v2(8.56,52.27) v2(8.56,50.47) v2(8.56,48.67) v2(8.56,46.87) v2(8.56,45.07) v2(8.56,43.27) v2(8.56,41.47) v2(8.56,39.67) v2(8.56,37.87) v2(10.31,36.01) v2(10.31,32.41) v2(10.31,30.61) v2(10.31,28.81) v2(10.36,54.07) v2(10.36,52.27) v2(10.36,50.47) v2(10.36,48.67) v2(10.36,46.87) v2(10.36,45.07) v2(10.36,43.27) v2(10.36,41.47) v2(10.36,39.67) v2(10.36,37.87) v2(12.11,36.01) v2(12.11,32.41) v2(12.11,30.61) v2(12.11,28.81) v2(12.16,54.07) v2(12.16,52.27) v2(12.16,50.47) v2(12.16,48.67) v2(12.16,46.87) v2(12.16,45.07) v2(12.16,43.27) v2(12.16,41.47) v2(12.16,39.67) v2(12.16,37.87) v2(12.54,33.71) v2(13.91,36.01) v2(13.91,34.21) v2(13.91,32.41) v2(13.91,30.61) v2(13.91,28.81) v2(13.96,54.07) v2(13.96,52.27) v2(13.96,50.47) v2(13.96,48.67) v2(13.96,46.87) v2(13.96,45.07) v2(13.96,43.27) v2(13.96,41.47) v2(13.96,39.67) v2(13.96,37.87) v2(14.83,29.8) v2(15.27,32.75) v2(15.71,36.01) v2(15.71,34.21) v2(15.71,28.81) v2(15.76,54.07) v2(15.76,52.27) v2(15.76,50.47) v2(15.76,48.67) v2(15.76,46.87) v2(15.76,45.07) v2(15.76,43.27) v2(15.76,41.47) v2(15.76,39.67) v2(15.76,37.87) v2(17.51,36.01) v2(17.51,34.21) v2(17.51,28.81) v2(17.56,54.07) v2(17.56,52.27) v2(17.56,50.47) v2(17.56,48.67) v2(17.56,46.87) v2(17.56,45.07) v2(17.56,43.27) v2(17.56,41.47) v2(17.56,39.67) v2(17.56,37.87) v2(17.59,32.65) v2(18.06,30.04) v2(19.31,36.01) v2(19.31,34.21) v2(19.31,32.41) v2(19.31,30.61) v2(19.31,28.81) v2(19.31,27.01) v2(19.36,54.07) v2(19.36,52.27) v2(19.36,50.47) v2(19.36,48.67) v2(19.36,46.87) v2(19.36,45.07) v2(19.36,43.27) v2(19.36,41.47) v2(19.36,39.67) v2(19.36,37.87) v2(21.11,36.01) v2(21.11,34.21) v2(21.11,32.41) v2(21.11,30.61) v2(21.11,28.81) v2(21.11,27.01) v2(21.16,54.07) v2(21.16,52.27) v2(21.16,50.47) v2(21.16,48.67) v2(21.16,46.87) v2(21.16,45.07) v2(21.16,43.27) v2(21.16,41.47) v2(21.16,39.67) v2(21.16,37.87) v2(22.91,36.01) v2(22.91,34.21) v2(22.91,32.41) v2(22.91,30.61) v2(22.91,28.81) v2(22.91,27.01) v2(22.96,54.07) v2(22.96,52.27) v2(22.96,50.47) v2(22.96,48.67) v2(22.96,46.87) v2(22.96,45.07) v2(22.96,43.27) v2(22.96,41.47) v2(22.96,39.67) v2(22.96,37.87) v2(30.97,45.31) v2(32.67,49.71) v2(32.67,47.91) v2(32.67,46.11) v2(32.67,44.31) v2(34.29,44.69) v2(34.47,49.71) v2(34.47,47.91) v2(34.47,46.11) v2(36,46.48) v2(36.27,49.71) v2(36.27,47.91) v2(56.75,45.58) v2(58.45,49.98) v2(58.45,48.18) v2(58.45,46.38) v2(58.45,44.58) v2(60.07,44.96) v2(60.25,49.98) v2(60.25,48.18) v2(60.25,46.38) v2(61.78,46.75) v2(62.05,49.98) v2(62.05,48.18) v2(75.85,54.12) v2(75.85,52.32) v2(75.85,50.52) v2(75.85,48.72) v2(75.85,43.32) v2(75.85,41.52) v2(75.85,39.72) v2(75.85,37.92) v2(75.8,36.06) v2(75.8,34.26) v2(75.8,32.46) v2(75.8,30.66) v2(75.8,28.86) v2(75.8,27.06) v2(76.19,47.27) v2(76.34,44.84) v2(77.6,36.06) v2(77.6,34.26) v2(77.6,32.46) v2(77.6,30.66) v2(77.6,28.86) v2(77.65,54.12) v2(77.65,52.32) v2(77.65,50.52) v2(77.65,48.72) v2(77.65,46.92) v2(77.65,45.12) v2(77.65,43.32) v2(77.65,41.52) v2(77.65,39.72) v2(77.65,37.92) v2(79.44,54.16) v2(79.44,52.36) v2(79.44,50.56) v2(79.44,48.76) v2(79.44,46.96) v2(79.44,45.16) v2(79.44,43.36) v2(79.44,41.56) v2(79.44,39.76) v2(79.44,37.96) v2(79.39,36.1) v2(79.39,34.3) v2(79.39,32.5) v2(79.39,30.7) v2(79.39,28.9) v2(79.39,27.1) v2(81.11,48.95) v2(81.24,52.36) v2(81.24,50.56) v2(81.24,45.16) v2(81.24,43.36) v2(81.24,37.96) v2(81.19,36.1) v2(81.19,32.5) v2(81.19,30.7) v2(81.19,28.9) v2(81.19,27.1) v2(81.36,39.25) v2(83.12,36.07) v2(83.12,32.47) v2(83.12,30.67) v2(83.12,28.87) v2(83.12,27.07) v2(83.17,52.33) v2(83.17,50.53) v2(83.17,45.13) v2(83.17,43.33) v2(83.18,39.25) v2(83.17,37.93)
BOOT: length 2.3
  TOP w0.2: U201.4 68.11,51.81 67.73,52.19 C225.1
CANH_SCL: length 39.9
  TOP w0.152: TP216.1 35.45,10.66 CON201.3
  PWR03 w0.152: v1(1.72,15.11) 2.11,15.11 3.07,16.07 17.39,16.07 18.95,17.63 28.92,17.63 34.85,11.7 34.85,11.21 CON201.3
CANL_SDA: length 42.1
  TOP w0.152: CON201.4 35.57,8.66 TP215.1
  PWR03 w0.152: CON201.4 34.3,9.27 35.56,10.53 35.56,11.67 29.19,18.04 2.07,18.04 v1(1.77,17.74)
COMP: length 2.7
  TOP w0.2: 70.89,46.97 71.46,46.97 72.09,46.34 72.49,46.34 R223.1
ESC_EN: length 46.9
  TOP w0.152: D2.1 82.38,25 R216.1 79.05,24.95 C216.1 78.03,24.85 R220.1
  TOP w0.2: 84.86,34.46 84.86,40.95 ; 84.86,34.46 84.84,34.44 Q206.1 ; 84.86,34.46 84.86,26.5 83.37,25.01 83.01,25.01 D2.1 ; 84.86,40.95 84.85,40.94 Q202.1 ; 84.86,40.95 84.86,47.48 ; Q203.1 84.82,47.44 84.86,47.48 ; 84.86,47.48 84.86,52.62 83.53,53.95 Q205.1
FSW: length 2.3
  TOP w0.2: 70.89,48.47 72.77,48.47 R231.2
ILIMIT: length 2.5
  TOP w0.2: R230.2 72.92,49.76 72.13,48.97 70.89,48.97
MODE: length 3.1
  TOP w0.2: R222.1 72.86,50.75 72.61,51 v1(72.55,51) ; 70.89,49.97 71.14,49.97 71.34,50.17 v1(71.34,50.93)
  PWR03 w0.2: v1(72.55,51) 72.48,50.93 v1(71.34,50.93)
PHASE: length 2.7
  TOP w0.2: R229.2 66.61,52.75 U201.6 U201.5
PWM1: length 69
  TOP w0.152: CON204.1 17.61,2.85 18.69,1.77 28.52,1.77 29.42,0.87 39.25,0.87 39.94,1.56 78.76,1.56 80.06,2.85 CON215.1
PWM2: length 70.8
  TOP w0.152: CON215.2 79.28,4.11 78.99,4.4 74.32,4.4 73.86,3.94 67.04,3.94 66.48,4.5 63.08,4.5 62.6,4.02 58.24,4.02 57.83,4.43 55.43,4.43 54.96,3.96 47,3.96 46.47,4.49 41.59,4.49 38.79,1.69 30.26,1.69 29.01,2.94 19.3,2.94 18.14,4.11 CON204.2
PWM3: length 69.5
  TOP w0.152: CON215.3 40.89,5.36 38.23,2.7 30.69,2.7 29.21,4.18 19.78,4.18 18.61,5.36 CON204.3
PWM4: length 69.7
  TOP w0.152: CON204.4 19.23,6.61 20.61,5.23 29.73,5.23 31.28,3.68 37.81,3.68 40.48,6.34 78.47,6.34 78.72,6.61 CON215.4
PWM5: length 70
  TOP w0.152: CON215.5 78.39,7.86 77.86,7.33 40.07,7.33 37.41,4.68 31.86,4.68 30.28,6.26 21.65,6.26 19.98,7.93 13.73,7.93 CON204.5
PWM6: length 70.2
  TOP w0.152: CON215.6 78.14,9.11 77.36,8.32 39.66,8.32 36.98,5.65 32.31,5.65 30.68,7.28 22.6,7.28 20.77,9.11 CON204.6
PWM7: length 70.4
  TOP w0.152: CON204.7 21.32,10.36 23.37,8.3 31.11,8.3 32.8,6.61 36.57,6.61 39.28,9.32 76.89,9.32 77.92,10.36 CON215.7
PWM8: length 70.6
  TOP w0.152: CON215.8 77.62,11.61 76.31,10.29 38.84,10.29 36.16,7.61 33.29,7.61 31.45,9.45 23.85,9.45 21.7,11.61 CON204.8
SW: length 6
  TOP w0.2: L202.1 65.64,42.79 R225.1
ULTRA: length 15.3
  TOP w0.2: v1(69.99,44.72) 69.61,45.1 U201.18 ; v1(75.37,45.96) 75.37,46.48 74.76,47.09 74.76,52.28 74.34,52.7 R221.1
  PWR03 w0.2: v1(75.37,45.96) 73.14,43.73 70.98,43.73 v1(69.99,44.72)
VDRV: length 2
  TOP w0.2: C228.1 68.61,43.95 U201.16
VFB: length 3.9
  TOP w0.2: R226.1 R227.2 72.84,46.95 72.15,46.95 71.64,47.46 70.89,47.46 70.89,47.47
VSENS: length 3.6
  TOP w0.2: C223.2 70.89,45.93 70.89,46.47
X86_PWR_EN: length 6.6
  TOP w0.2: TP217.1 72.57,53.96 72.48,53.87 72.47,53.87 72.45,53.85 R224.1 71.34,53.22 71.34,52.11 71.04,51.81 69.69,51.81 69.41,51.53 U201.2
N8283759: length 6.6
  TOP w0.2: Q204.1 78.83,21.2 R217.1 76.55,22.53 C217.1 ; TP206.1 76.3,24.15 C217.1 ; R219.2 75.98,22.22 C217.1
N15887710: length 1.3
  TOP w0.152: Q204.3 79.63,23.31 R220.2
N17226372: length 2.5
  TOP w0.2: R205.2 47.35,42.58 C205.2 48.34,43.56 C206.1
N17226390: length 1
  TOP w0.2: R207.2 48.39,44.53 C213.2
N17226393: length 1
  TOP w0.2: C214.2 41.5,53.65 R209.1
N17226422: length 2.2
  TOP w0.2: C215.1 45.26,44.43 44.53,45.16 U200.19
N17229988: length 2.5
  TOP w0.2: C223.1 73.05,42.79 C219.2 73.03,42.79 R225.2
N17230026: length 1
  TOP w0.2: C233.2 74.06,45.77 R223.2
N17230033: length 1
  TOP w0.2: C225.2 67.73,53.88 R229.1
N17230097: length 2.3
  TOP w0.2: C224.1 70.95,44.6 70.11,45.44 U201.19

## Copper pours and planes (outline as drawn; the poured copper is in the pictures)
12V-OUT on TOP: 69.44,19.57 69.44,16 70.11,15.33 70.11,12.08 71.04,11.15 73.52,11.15 75.15,12.78 77.13,12.78 77.83,13.48 77.83,18.95 77.05,19.73 69.6,19.73
19V_AIBOX_OUT on TOP: 45.81,20.57 53.76,20.57 55.13,19.2 56.62,14.77 57.03,14.36 57.03,12.87 55.57,11.41 52.34,11.41 51.82,11.93 51.82,14.26 49.89,16.19 45.79,16.19 45.42,16.56 45.42,20.18
19V_FMU_OUT on TOP: 25.02,18.43 25.02,15.14 23.9,14.02 23.9,10.33 23.98,10.25 26.91,10.25 28.17,11.51 28.17,12.79 28.98,13.6 28.98,18.41 28.83,18.56 25.15,18.56
19V_SW on TOP: 40.5,45.84 40.5,45.56 39.24,44.3 37.41,44.3 37.19,44.08 37.19,40.66 37.39,40.46 41.48,40.46 41.63,40.61 41.63,44.25 42.07,44.69 42.07,45.92 42.05,45.95 40.6,45.95
AGND on PWR03: 43.62,49.57 43.62,46.61 45.47,44.76 45.47,44.18 45.84,43.81 46.42,43.81 48.98,46.37 48.98,48.83 50.57,50.42 51.02,50.42 51.97,51.37 68.43,51.37 69.14,50.66 69.14,47.93 69.08,47.87 69.08,46.75 70.88,44.95 70.88,44.41 71.2,44.09 72.26,44.09 74.73,46.56 74.73,51.55 71.51,54.77 70.45,54.77 70.28,54.6 70.28,54.11 69.73,53.56 69.69,53.56 69.15,53.02 53.27,53.02 51.52,54.77 44.26,54.77 44,54.51 44,49.95
GND on TOP: 50.77,50.75 50.77,54.8 65.24,54.8 65.24,51.48 65.05,51.29 57.62,51.29 56.34,50.01 56.34,48.85 54.79,47.3 54.79,38.59 55.66,37.72 55.68,37.72 55.89,37.51 56.24,37.51 56.27,37.48 56.27,35.56 55.9,35.19 55.9,30.1 56.17,29.83 56.17,29.3 55.62,28.75 51.55,28.75 50.77,29.53 50.76,29.53 50.38,29.91 45.16,29.91 44.27,30.79 44.27,31 45.01,31.74 45.01,41.71 45.25,41.95 49.04,41.95 50.12,43.03 50.12,50.1
GND on TOP: 1,0.2 0.43,0.43 0.2,1 0.2,26.93 0.34,27.07 17.16,27.07 18.82,25.41 18.82,24.5 19.61,23.72 23.84,23.72 23.84,14.46 23.46,14.08 23.46,10.35 23.93,9.88 27.25,9.88 29.57,12.2 29.57,18.79 32.51,21.73 43.92,21.73 44.46,21.19 44.46,16.13 45.48,15.11 49.66,15.11 51.2,13.57 51.2,11.77 52.34,10.63 55.54,10.63 57.11,12.2 57.63,12.67 57.58,14.66 56.16,18.9 56.16,20.54 57.68,22.06 68.14,22.06 68.36,21.84 68.36,16.34 69.19,15.51 69.19,12.29 70.87,10.61 73.71,10.61 75.3,12.2 77.45,12.2 78.55,13.3 78.55,19.25 79.05,19.75 83.13,19.75 84.36,20.98 84.36,24.85 84.52,25.39 84.94,25.76 99.8,25.76 99.8,1 99.57,0.43 99,0.2
GND on TOP: 25.75,28.75 25.24,29.26 25.24,54.8 39.71,54.8 39.71,51.28 39.38,50.95 31.75,50.95 30.81,50.01 30.81,48.85 29.26,47.3 29.26,38.59 30.13,37.72 30.64,37.72 30.84,37.52 30.84,35.66 30.37,35.19 30.37,30.1 30.64,29.83 30.64,29.05 30.34,28.75
GND on TOP: 74.62,30.31 74.62,41.97 74.35,42.1 74.05,42.15 71.72,42.15 71.17,41.99 70.8,41.55 70.8,30.51 71.2,30.11 74.42,30.11
GND on BOTTOM, PWR03, PWR04, PWR05: 1,0.2 0.43,0.43 0.2,1 0.2,26.77 16.56,26.77 17.28,26.05 99.75,26.05 99.8,26 99.8,1 99.57,0.43 99,0.2
GND on PWR02: 1,0.2 0.43,0.43 0.2,1 0.2,54 0.43,54.57 1,54.8 99,54.8 99.57,54.57 99.8,54 99.8,1 99.57,0.43 99,0.2
VBAT_ESC on BOTTOM, PWR03, PWR04, PWR05: 84.92,26.62 84.92,54.8 99,54.8 99.57,54.57 99.8,54 99.8,26.62
VDD_12V_SYS on TOP: 56.77,37.42 56.77,29.15 56.05,28.43 56.05,23.7 57.01,22.74 72.7,22.74 73.39,23.43 73.39,28.89 72.74,29.54 70.48,29.54 67.19,32.83 67.19,34.17 67.13,34.23 63.25,34.23 63.1,34.08 63.1,31.9 62.71,31.51 59.62,31.51 59.3,31.83 59.3,37.42 59.2,37.52 56.87,37.52
VDD_19V_SYS on TOP: 31.26,37.51 31.26,28.9 30.7,28.34 26.93,28.34 25.72,27.12 25.72,20.12 26.09,19.75 29.31,19.75 32.05,22.49 51.22,22.49 51.57,22.84 51.57,27.79 50.07,29.29 44.97,29.29 41.68,32.58 41.68,33.92 41.28,34.32 37.27,34.32 36.78,33.83 36.78,31.94 36.1,31.26 34.11,31.26 33.79,31.58 33.79,37.47 33.7,37.55 31.3,37.55
BATT_IN on TOP: 30.47,38.1 33.21,38.1 33.5,38.39 33.5,43.26 37.91,47.67 38.61,47.67 39.52,48.58 42.89,48.58 43.1,48.79 43.1,49.59 42.96,49.73 39.98,49.73 39.27,50.44 32.25,50.44 31.3,49.49 31.3,48.37 30.42,47.49 30.42,38.15
BATT_IN on TOP: 59.2,43.56 63.61,47.97 64.31,47.97 65.22,48.88 68.59,48.88 68.8,49.09 68.8,49.89 68.66,50.03 65.68,50.03 64.97,50.74 57.95,50.74 57,49.79 57,48.67 56.21,47.88 56.21,38.14 56.26,38.09 58.98,38.09 59.2,38.31
BATT_IN on TOP: 75.18,54.51 75.18,47.49 75.97,46.7 75.97,45.32 75.18,44.53 75.18,26.7 75.97,25.91 83.16,25.91 84.46,27.21 84.46,33 84.3,33.16 80.43,33.16 80.29,33.3 80.29,35.31 80.47,35.49 84.29,35.49 84.49,35.69 84.49,39.52 84.3,39.71 80.47,39.71 80.32,39.86 80.32,41.73 80.53,41.94 84.27,41.94 84.46,42.13 84.46,45.87 84.05,46.28 80.52,46.28 80.35,46.45 80.35,48.35 80.48,48.48 84.29,48.48 84.52,48.71 84.52,52.19 83.84,52.87 80.85,52.87 80.58,53.14 80.58,54.51 80.43,54.66 75.33,54.66
BATT_IN on TOP: 0.2,27.63 0.2,54 0.43,54.57 1,54.8 24.58,54.8 24.58,24.53 24.46,24.42 24.35,24.4 24.24,24.39 19.85,24.39 19.67,24.57 19.67,25.3 17.34,27.63
BATT_IN on BOTTOM, PWR03, PWR04, PWR05: 0.2,27.72 0.2,54 0.43,54.57 1,54.8 84.02,54.8 84.02,27.21 83.68,26.87 18.39,26.87 17.54,27.72
SW on TOP: 66.2,45.86 66.2,45.58 64.94,44.32 63.11,44.32 63.03,44.24 63.03,40.54 63.09,40.48 67.18,40.48 67.33,40.63 67.33,44.27 67.77,44.71 67.77,45.94 67.75,45.97 66.31,45.97

Small or netless copper shapes (teardrops, artwork), in the pictures only: 1 on TOP

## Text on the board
Ref Des/Silkscreen Top: SCL_CANL | SDA_CANH | GND | PWM7 | PWM8 | PWM5 | PWM2 | PWM1 | PWM3 | PWM6 | PWM4 | NC | 21V~34V@Max40A | 12AWG | BATT- | BATT+ | 19V | 12V | Flycore_PDB_V3 | D.D:20260625 | V- | V+ | Max@40A
User.6: FIGURE | SIZE | 0.3 | 0.6 | 0.7 | 1.0 | 1.9 | 2.2 | 2.9 | 1.9x0.8 | DRILL CHART: TOP to BOTTOM | ALL UNITS ARE IN MILLIMETERS | PLATED | QTY | 334 | 664 | 2 | 4
